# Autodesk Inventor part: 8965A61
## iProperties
Author: REED
Created: 2002-02
Part Number: 8965A61
Material: Steel, Mild
Document SubType Name: Modeling
Designer: REED
Control State: 0
Master: False
Checked Out: False
Last Check In By: roreen
Last Check In Date: 2002-02-20
PropertySet Name: Design Tracking Control
Shininess: 70.0
Length Units: 11272
Angle Units: 11286
Time Units: 11279
Mass Units: 11290
Length Display Precision: 3
Angle Display Precision: 2
Compacted: True
PropertySet Name: _Private Model Information
Density: 0.0
Volumn: 0.0
Area: 0.0
PropertySet Name: Model Information
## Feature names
1. Extrusion2
2. Extrusion3
3. Rectangular Pattern1
4. Extrusion4
5. Rectangular Pattern2
6. Extrusion5
7. Rectangular Pattern3
8. Extrusion6
9. Extrusion7
